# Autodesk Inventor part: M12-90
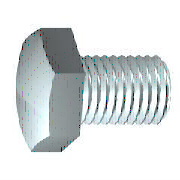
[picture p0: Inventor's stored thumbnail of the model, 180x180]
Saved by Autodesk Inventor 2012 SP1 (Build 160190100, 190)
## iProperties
Created: 2006-02
Material: Steel, Mild
Description: ISO metric hexagon commercial bolts and screws
Document SubType Name: Modeling
Standard: AS 1111
Designer: Administrator
Standards Organization: AS
Language: en-US
Categories: <MemberInstance><Categories><Category DisplayName="Fasteners" InternalName="e4da775c-781d-43d5-af7c-5136215cf5a6" Mnemonic="FSTN"><Category DisplayName="Bolts"
Density: 1 g/cm^3
Author: Administrator
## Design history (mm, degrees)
workplane "Work Plane1"
revolve "Body" stored, may be unused: angle "d12" = 90 deg
sketch "Sketch2"
  geometry: L1 (0, 10.392)-(9, 5.196); L2 (9, 5.196)-(9, -5.196); L3 (9, -5.196)-(0, -10.392); L4 (0, -10.392)-(-9, -5.196); L5 (-9, -5.196)-(-9, 5.196); L6 (-9, 5.196)-(0, 10.392); 2 further points
  constraints: 12 end point, 1 coincident, 1 vertical, 11 other
  dimensions: "d11" = 18 distance between parallel lines of L5 L2 (= SW)
extrude "Head" join sketch "Sketch2" distance "d3" = 7.35 (= KOH - SD); taper "d4" = 0 deg
revolve "Chamfer1" stored, may be unused: angle "d21" = 90 deg
body "Solid1"
feature "Thread" dims "d15" = 30 (= GEL), "d16" = 0
chamfer "Chamfer2" distance "d6" = 1.07354 (= -0.5 x SPD + 0.5 x GD); stored, may be unused: second distance "d7" = 1.07364 (computed from GUL), angle "d55" = 45 deg
sketch "Sketch1"
  geometry: L1 (0, 9)-(0, 6); L2 (60, 6)-(90, 6); L3 (90, 6)-(90, 0); L4 (90, 0)-(-0.6, 0); L5 (-18.72, 0)-(108.12, 0) reference; L6 (-0.6, 0)-(-0.6, 9); L7 (-0.6, 9)-(0, 9); L8 (60, 6)-(58.926, 6); L9 (58.926, 6)-(0, 6); L10 (0, -1.8)-(0, 10.8) reference
  constraints: 16 end point, 2 collinear, 2 perpendicular, 1 parallel
  dimensions: "d0" = 90 distance between parallel lines of L3 L1 (= NLG); "d1" = 30 distance from line of L2.start L3 (= GEL); "d2" = 12 diameter of L2 L4 (= GD); "d9" = 0.6001 distance between parallel lines of L6 L1 (computed from SD); "d10" = 18 diameter of L7 L4 (= SD2); "d13" = 1.07364 distance of L2.start L8.end (computed from GAL); "d14" = 12 diameter of L9 L4 (= BDM)
sketch "Sketch4"
  geometry: L1 (-7.95, 9)-(-7.95, 10.392); L2 (-7.95, 10.392)-(-7.146, 10.392); L3 (-7.146, 10.392)-(-7.95, 9); L4 (-9.42, 0)-(0.87, 0) reference; L5 (-0.6, 10.392)-(-7.95, 10.392) reference; L6 (-7.95, 5.196)-(-7.95, 10.392) reference
  constraints: 6 end point, 2 collinear, 1 perpendicular, 1 vertical
  dimensions: "d5" = 30 deg angle of L3 L1 (= ANG1); "d19" = 18 diameter of L1.start L4 (= SW0)
other parameters: "NLG" = 90 [user parameter; used in 1 equation term], "GD" = 12 (= NND) [user parameter; used in 2 equation terms], "BDM" = 12 (= NND) [user parameter; used in 1 equation term], "KOH" = 7.95 [user parameter; used in 1 equation term], "GEL" = 30 [user parameter; used in 2 equation terms], "SW" = 18 [user parameter; used in 5 equation terms], "SW0" = 18 (= SW) [user parameter; used in 1 equation term], "SPD" = 9.85293 (= NND - 1.2269 x PTC) [user parameter; used in 1 equation term], "SD2" = 18 (= SW) [user parameter; used in 1 equation term], "SD" = 0.6 [user parameter; used in 3 equation terms], "ANG1" = 30 deg [user parameter; used in 1 equation term], "GAL" = 1.07354 (= 0.61345 x PTC) [user parameter; used in 1 equation term], "GUL" = 1.07354 (= 0.61345 x PTC) [user parameter; used in 1 equation term], "d8" = 0, "RR" = 0.6 [user parameter], "d57" = 0, "d58" = 0, "TPU" = 5.71429 (computed from PTC) [user parameter], "WFT" = 0.6 (= SD) [user parameter], "GD1" = 9.85293 (= THREADDIA - 1.2269 x PTC) [user parameter], "THREADDIA" = 12 [user parameter; used in 1 equation term], "SDH" = 18 (= SW) [user parameter], "TOA" = 30 deg [user parameter], "FAWI" = 45 deg [user parameter], "PTC" = 1.75 [user parameter; used in 5 equation terms], "NND" = 12 [user parameter; used in 3 equation terms], "E0" = 20.79 (= 1.155 x SW) [user parameter]
